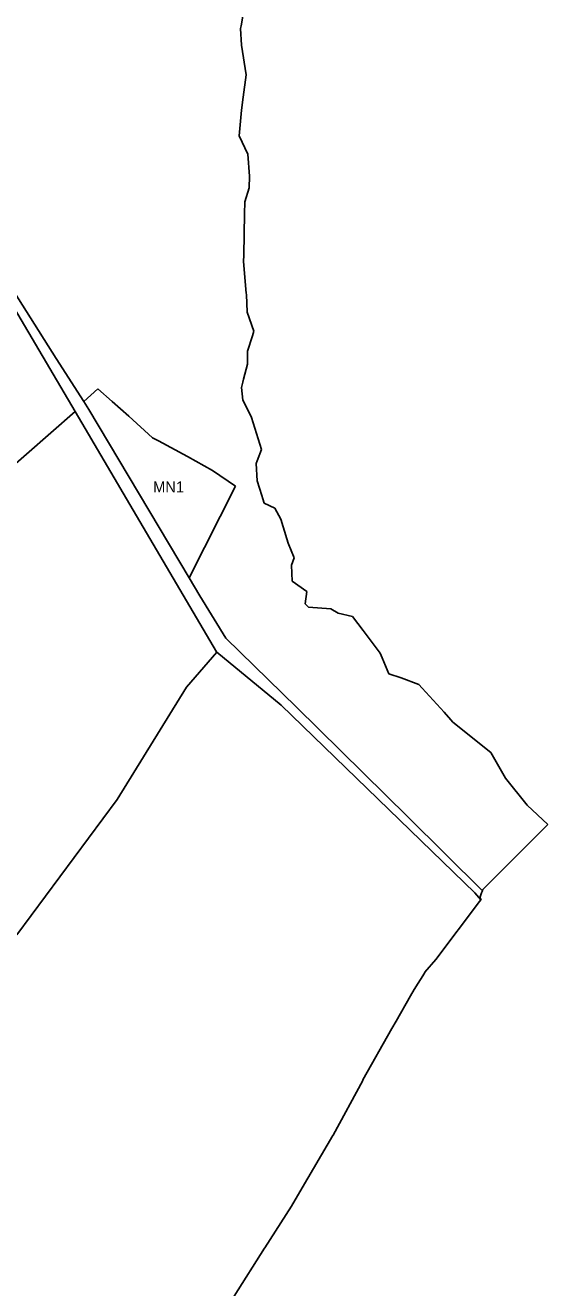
# Model space of a CAD drawing. Extents: x 7435758 to 7439981, y 5550649 to 5554049.
# Drawn here: x 7439733 to 7439981, y 5552845 to 5553445 of the extents above; entities that cross this region are included whole.
import ezdxf

# ---------------------------------------------------------------- set-up
doc = ezdxf.new("R2010")
doc.units = 0
doc.layers.add('linie_rozgraniczające', color=7, linetype='Continuous')
doc.layers.add('oznaczenia_przeznaczen', color=7, linetype='Continuous')

msp = doc.modelspace()

# ---------------------------------------------------------------- linework, layer by layer
at = {"layer": 'linie_rozgraniczające'}
for p, q in [((7439837.74, 5553455.94), (7439835.78, 5553444.79)), ((7439835.78, 5553444.79), (7439835.56, 5553443.54)), ((7439835.56, 5553443.54), (7439836.05, 5553435.64)), ((7439836.05, 5553435.64), (7439838.25, 5553421.48)), ((7439838.25, 5553421.48), (7439836.79, 5553410.83)), ((7439836.79, 5553410.83), (7439835.95, 5553404.71)), ((7439835.95, 5553404.71), (7439834.94, 5553392.49)), ((7439834.94, 5553392.49), (7439839.02, 5553383.87)), ((7439839.02, 5553383.87), (7439839.82, 5553373.41)), ((7439839.82, 5553373.41), (7439839.62, 5553367.85)), ((7439839.62, 5553367.85), (7439837.58, 5553361.13)), ((7439748.06, 5553286.69), (7439703.19, 5553357.69)), ((7439837.58, 5553361.13), (7439837.46, 5553355.42)), ((7439837.46, 5553355.42), (7439837.26, 5553345.78)), ((7439837.26, 5553345.78), (7439837.06, 5553335.9)), ((7439837.06, 5553335.9), (7439837, 5553332.75)), ((7439837, 5553332.75), (7439838.27, 5553317.73)), ((7439838.27, 5553317.73), (7439838.33, 5553317.13)), ((7439838.33, 5553317.13), (7439838.65, 5553308.8)), ((7439726.22, 5553313.97), (7439757.05, 5553261.56)), ((7439838.65, 5553308.8), (7439841.86, 5553299.67)), ((7439841.2, 5553297.6), (7439838.89, 5553290.32)), ((7439841.86, 5553299.67), (7439841.2, 5553297.6)), ((7439761.15, 5553266.28), (7439748.06, 5553286.69)), ((7439838.89, 5553290.32), (7439838.76, 5553284.12)), ((7439838.76, 5553284.12), (7439836.94, 5553276.97)), ((7439836.58, 5553275.58), (7439835.91, 5553272.94)), ((7439835.91, 5553272.94), (7439836.66, 5553266.92)), ((7439836.94, 5553276.97), (7439836.58, 5553275.58)), ((7439767.84, 5553272.4), (7439761.15, 5553266.28)), ((7439774.65, 5553266.36), (7439767.84, 5553272.4)), ((7439836.66, 5553266.92), (7439836.85, 5553266.54)), ((7439757.05, 5553261.56), (7439722.38, 5553231.16)), ((7439757.05, 5553261.56), (7439786.17, 5553212.04)), ((7439763.57, 5553262.51), (7439761.15, 5553266.28)), ((7439811.19, 5553182.58), (7439763.57, 5553262.51)), ((7439782.48, 5553259.39), (7439774.65, 5553266.36)), ((7439836.85, 5553266.54), (7439840.75, 5553258.73)), ((7439793.78, 5553249.03), (7439782.48, 5553259.39)), ((7439840.75, 5553258.73), (7439840.76, 5553258.7)), ((7439840.76, 5553258.7), (7439845.51, 5553243.61)), ((7439796.53, 5553247.7), (7439793.78, 5553249.03)), ((7439810.35, 5553240.21), (7439796.53, 5553247.7)), ((7439845.51, 5553243.61), (7439843.47, 5553238.15)), ((7439822.25, 5553233.53), (7439810.35, 5553240.21)), ((7439843.47, 5553238.15), (7439843.02, 5553236.95)), ((7439843.02, 5553236.95), (7439843.39, 5553228.59)), ((7439833.15, 5553226.11), (7439822.25, 5553233.53)), ((7439811.19, 5553182.58), (7439833.15, 5553226.11)), ((7439843.39, 5553228.59), (7439845.62, 5553221.73)), ((7439845.62, 5553221.73), (7439846.16, 5553220.07)), ((7439846.16, 5553220.07), (7439846.79, 5553218.12)), ((7439846.79, 5553218.12), (7439851.88, 5553215.65)), ((7439851.88, 5553215.65), (7439854.6, 5553210.39)), ((7439786.17, 5553212.04), (7439824.05, 5553147.49)), ((7439854.6, 5553210.39), (7439855.76, 5553206.77)), ((7439855.76, 5553206.77), (7439858.21, 5553199.09)), ((7439858.21, 5553199.09), (7439860.93, 5553192.09)), ((7439860.93, 5553192.09), (7439859.66, 5553188.64)), ((7439859.66, 5553188.64), (7439860.08, 5553180.94)), ((7439816.24, 5553174.11), (7439811.19, 5553182.58)), ((7439860.08, 5553180.94), (7439866.96, 5553176.05)), ((7439828.58, 5553153.88), (7439816.24, 5553174.11)), ((7439866.96, 5553176.05), (7439866.17, 5553170.16)), ((7439866.17, 5553170.16), (7439866.69, 5553169.69)), ((7439866.69, 5553169.69), (7439867.83, 5553168.68)), ((7439867.83, 5553168.68), (7439878.42, 5553167.89)), ((7439878.42, 5553167.89), (7439881.85, 5553165.76)), ((7439881.85, 5553165.76), (7439888.61, 5553164.3)), ((7439888.61, 5553164.3), (7439893.75, 5553157.52)), ((7439862.15, 5553121.22), (7439828.58, 5553153.88)), ((7439893.75, 5553157.52), (7439894.7, 5553156.27)), ((7439894.7, 5553156.27), (7439901.85, 5553146.85)), ((7439809.8, 5553130.68), (7439824.25, 5553147.33)), ((7439824.05, 5553147.49), (7439824.25, 5553147.33)), ((7439824.25, 5553147.33), (7439854.85, 5553122.16)), ((7439901.85, 5553146.85), (7439902.79, 5553144.53)), ((7439902.79, 5553144.53), (7439905.89, 5553136.94)), ((7439905.89, 5553136.94), (7439911.7, 5553135.12)), ((7439911.7, 5553135.12), (7439920.18, 5553131.88)), ((7439776.92, 5553077.3), (7439809.8, 5553130.68)), ((7439920.18, 5553131.88), (7439921.71, 5553130.12)), ((7439921.71, 5553130.12), (7439932.11, 5553118.71)), ((7439854.85, 5553122.16), (7439946.7, 5553033.04)), ((7439914.94, 5553069.14), (7439862.15, 5553121.22)), ((7439932.11, 5553118.71), (7439935.33, 5553115.16)), ((7439935.33, 5553115.16), (7439936.35, 5553114.04)), ((7439936.35, 5553114.04), (7439954.4, 5553099.6)), ((7439954.4, 5553099.6), (7439961.29, 5553087.41)), ((7439961.29, 5553087.41), (7439971.62, 5553074.6)), ((7439729.26, 5553013.06), (7439776.92, 5553077.3)), ((7439950.32, 5553033.89), (7439914.94, 5553069.14)), ((7439971.62, 5553074.6), (7439981.35, 5553065.42)), ((7439980.28, 5553064.31), (7439978.3, 5553062.33)), ((7439981.35, 5553065.42), (7439980.28, 5553064.31)), ((7439978.3, 5553062.33), (7439950.55, 5553034.58)), ((7439946.7, 5553033.04), (7439949.59, 5553029.62)), ((7439949.98, 5553032.93), (7439949.15, 5553030.6)), ((7439950.32, 5553033.89), (7439949.98, 5553032.93)), ((7439950.55, 5553034.58), (7439950.32, 5553033.89)), ((7439948.97, 5553028.81), (7439928.16, 5553001.38)), ((7439949.59, 5553029.62), (7439948.97, 5553028.81)), ((7439949.15, 5553030.6), (7439949.76, 5553029.84)), ((7439949.76, 5553029.84), (7439949.59, 5553029.62)), ((7439928.16, 5553001.38), (7439923.07, 5552995.32)), ((7439922.79, 5552994.9), (7439918, 5552987.06)), ((7439923.07, 5552995.32), (7439922.79, 5552994.9)), ((7439918, 5552987.06), (7439916.17, 5552984.07)), ((7439916.17, 5552984.07), (7439909.36, 5552971.96)), ((7439907.4, 5552968.48), (7439893.64, 5552944.14)), ((7439909.36, 5552971.96), (7439907.4, 5552968.48)), ((7439893.51, 5552943.89), (7439879.47, 5552917.91)), ((7439893.64, 5552944.14), (7439893.51, 5552943.89)), ((7439879.41, 5552917.8), (7439864.72, 5552892.88)), ((7439879.47, 5552917.91), (7439879.41, 5552917.8)), ((7439864.7, 5552892.85), (7439859.69, 5552884.24)), ((7439864.72, 5552892.88), (7439864.7, 5552892.85)), ((7439859.69, 5552884.24), (7439847.01, 5552864.42)), ((7439846.87, 5552864.2), (7439832.42, 5552841.4)), ((7439847.01, 5552864.42), (7439846.87, 5552864.2))]:
    msp.add_line(p, q, dxfattribs=at)

# ---------------------------------------------------------------- texts
at = {"layer": 'oznaczenia_przeznaczen'}
msp.add_text('MN1', height=5.2, dxfattribs=at).set_placement((7439794.02, 5553223.15))

doc.saveas('drawing.dxf')
